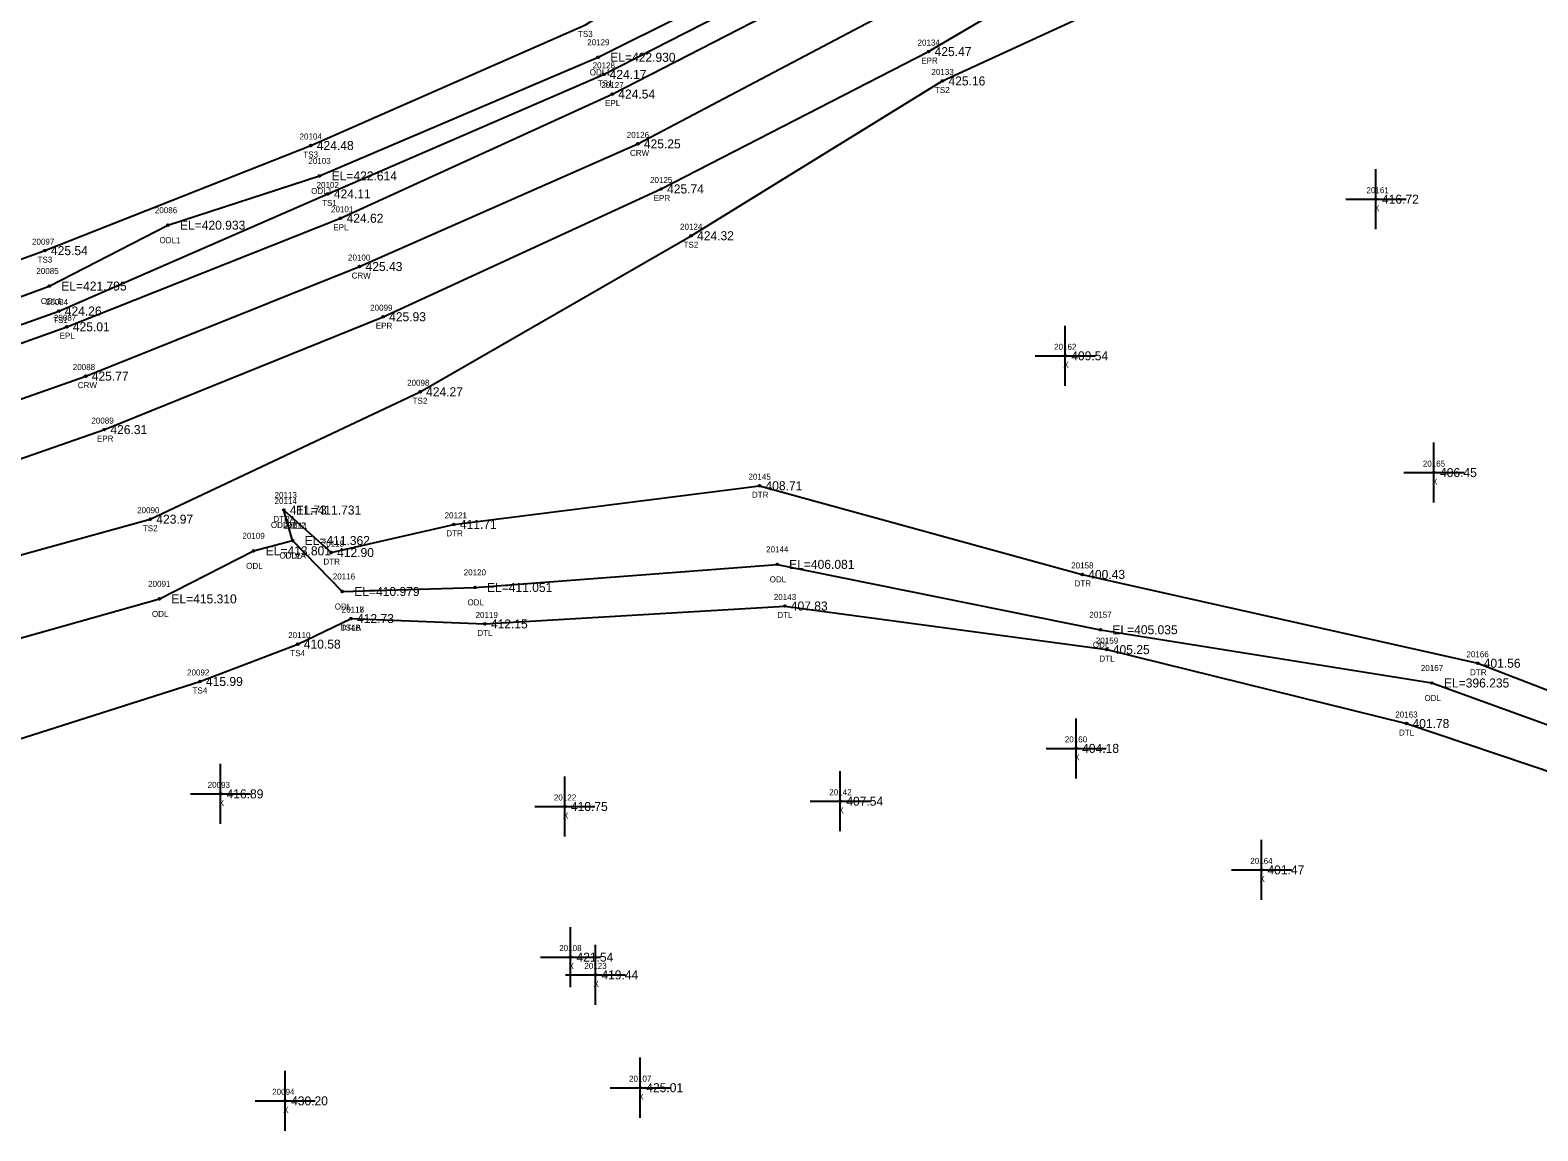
# Model space of a CAD drawing. Extents: x 2116373 to 2118139, y 979529 to 981026.
# Drawn here: x 2116755.3 to 2117006.3, y 979585.4 to 979768.8 of the extents above; entities that cross this region are included whole.
import ezdxf

# ---------------------------------------------------------------- set-up
doc = ezdxf.new("R2010")
doc.units = 0
for name, color, linetype in [('RD_DTM_BkLn1', 7, 'Continuous'), ('RD_DTM_BkLn2', 7, 'Continuous'), ('RD_DTM_BkLn_txCode', 7, 'Continuous'), ('RD_EX_H2O', 7, 'Continuous'), ('RD_EX_H2O_txCode', 7, 'Continuous'), ('RD_EX_Misc', 7, 'Continuous'), ('RD_EX_Misc_txCode', 7, 'Continuous'), ('RD_EX_Road', 7, 'Continuous'), ('RD_EX_Road_txCode', 7, 'Continuous'), ('RD_EX_TX_H2O_ELEV', 7, 'Continuous'), ('RD_EX_TX_Misc_ELEV', 7, 'Continuous'), ('RD_EX_TX_Road_ELEV', 7, 'Continuous'), ('RD_HC_Survey_ELEV', 7, 'Continuous'), ('RD_HC_Survey_txCode', 7, 'Continuous'), ('RD_SMD_Locator', 7, 'Continuous')]:
    doc.layers.add(name, color=color, linetype=linetype)

msp = doc.modelspace()

# ---------------------------------------------------------------- linework, layer by layer
at = {"layer": 'RD_DTM_BkLn1'}
msp.add_lwpolyline([(2116414.21, 979630.19), (2116468.62, 979643.23), (2116521.45, 979653.6), (2116618.87, 979670.38), (2116668.4, 979680.7), (2116717.3, 979694.48), (2116764.56, 979711.13), (2116810.15, 979729.38), (2116856.49, 979749.81), (2116900.74, 979773.15), (2116944.03, 979798.93), (2116982.75, 979824.6), (2117026.56, 979857.02), (2117064.34, 979888.81), (2117101.78, 979922.69), (2117176.3, 979989.4), (2117250.99, 980056.19), (2117326.56, 980126.36)], dxfattribs=at)
at = {"layer": 'RD_DTM_BkLn2'}
for points in [[(2116410.78, 979641.79), (2116465.45, 979654.97), (2116518.83, 979664.89), (2116614.96, 979683.75), (2116663.75, 979692.58), (2116713.02, 979705.22), (2116760.07, 979721.97), (2116804.88, 979741.47), (2116850.79, 979761.38), (2116894.83, 979783.88), (2116937.98, 979807.44), (2116977.39, 979833.6), (2117020.56, 979865.29), (2117056.86, 979896.38), (2117094.29, 979932.2), (2117168.14, 979997.38), (2117238.71, 980069.61), (2117312.33, 980134.21), (2117318.43, 980135.16)], [(2116408.48, 979653.74), (2116461.38, 979665.42), (2116520.7, 979678.48), (2116616.28, 979695.74), (2116661.37, 979703.79), (2116711.18, 979715.21), (2116757.77, 979732.03), (2116802.04, 979749.54), (2116847.76, 979769.63), (2116889.13, 979795.82), (2116931.32, 979820.72), (2116972.01, 979847.71), (2117009.67, 979877.33), (2117051.05, 979910.18), (2117086.71, 979942.74), (2117161.4, 980003.96), (2117222.13, 980080.24), (2117265.44, 980120.03)], [(2116417.57, 979618.2), (2116471.29, 979630.11), (2116523.91, 979640.31), (2116563.87, 979646.21), (2116622.92, 979650.9), (2116673.37, 979660.68), (2116721.38, 979672.44), (2116775.31, 979687.3), (2116820.23, 979708.52), (2116865.35, 979734.51), (2116907.21, 979760.29), (2116934.42, 979772.82), (2116951.5, 979788.78), (2116990.39, 979814.35), (2117033.97, 979847.22), (2117071.26, 979879.46), (2117111.32, 979914.45), (2117184.14, 979980.37), (2117264.18, 980040.84), (2117335.34, 980108.05), (2117336.43, 980115.6)], [(2116420.33, 979611.17), (2116472.25, 979624.85), (2116526.15, 979634.55), (2116564.74, 979640.45), (2116627.58, 979623.31), (2116680.58, 979618.75), (2116744.33, 979647.79), (2116783.58, 979660.27), (2116799.87, 979666.49), (2116808.73, 979670.75)]]:
    msp.add_lwpolyline(points, dxfattribs=at)
at = {"layer": 'RD_EX_H2O'}
msp.add_line((2116799, 979683.75), (2116797.55, 979688.83), dxfattribs=at)
for points in [[(2116411.09, 979644.42), (2116463.93, 979657.73), (2116517.88, 979668.38), (2116615.09, 979686.35), (2116663.35, 979695.16), (2116711.62, 979708.91), (2116758.49, 979726.13), (2116778.25, 979736.27), (2116803.5, 979744.47), (2116849.89, 979764.23), (2116894.14, 979786.32), (2116936.31, 979809.39), (2116976.21, 979834.9), (2117018.41, 979867.86), (2117054.24, 979898.91), (2117093.35, 979934.14), (2117166.11, 979999.69), (2117224.07, 980077.92), (2117265.44, 980120.03)], [(2116797.55, 979688.83), (2116805.41, 979681.75), (2116825.86, 979686.44), (2116876.74, 979692.87), (2116930.48, 979678.1), (2116996.33, 979663.31), (2117099.87, 979623.34), (2117144.47, 979607.97), (2117167, 979599.31)], [(2116419.35, 979615.24), (2116471.51, 979627.15), (2116524.74, 979637.29), (2116564.01, 979643.4), (2116629.25, 979631.55), (2116678.97, 979635.46), (2116738.46, 979663.21), (2116776.82, 979674.03), (2116792.52, 979682.03), (2116799, 979683.75), (2116807.27, 979675.26), (2116829.37, 979675.94), (2116879.68, 979679.78), (2116933.5, 979668.89), (2116988.71, 979660.02), (2117093.78, 979621.95), (2117143.56, 979603.85), (2117167, 979599.31)], [(2116808.73, 979670.75), (2116831.02, 979669.86), (2116880.96, 979672.84), (2116934.58, 979665.58), (2116984.47, 979653.27), (2117095.62, 979615.8), (2117142.6, 979599.29), (2117167, 979599.31)]]:
    msp.add_lwpolyline(points, dxfattribs=at)
at = {"layer": 'RD_EX_Misc'}
for p, q in [((2116979.39, 979735.6), (2116979.39, 979745.6)), ((2116974.39, 979740.6), (2116984.39, 979740.6)), ((2116927.65, 979709.51), (2116927.65, 979719.51)), ((2116922.65, 979714.51), (2116932.65, 979714.51)), ((2116989.05, 979690.06), (2116989.05, 979700.06)), ((2116984.05, 979695.06), (2116994.05, 979695.06)), ((2116929.47, 979644.13), (2116929.47, 979654.13)), ((2116924.47, 979649.13), (2116934.47, 979649.13)), ((2116787.01, 979636.55), (2116787.01, 979646.55)), ((2116844.34, 979634.45), (2116844.34, 979644.45)), ((2116890.2, 979635.33), (2116890.2, 979645.33)), ((2116782.01, 979641.55), (2116792.01, 979641.55)), ((2116839.34, 979639.45), (2116849.34, 979639.45)), ((2116885.2, 979640.33), (2116895.2, 979640.33)), ((2116960.32, 979623.89), (2116960.32, 979633.89)), ((2116955.32, 979628.89), (2116965.32, 979628.89)), ((2116845.27, 979609.36), (2116845.27, 979619.36)), ((2116840.27, 979614.36), (2116850.27, 979614.36)), ((2116849.42, 979606.41), (2116849.42, 979616.41)), ((2116844.42, 979611.41), (2116854.42, 979611.41)), ((2116856.89, 979587.62), (2116856.89, 979597.62)), ((2116797.75, 979585.43), (2116797.75, 979595.43)), ((2116851.89, 979592.62), (2116861.89, 979592.62)), ((2116792.75, 979590.43), (2116802.75, 979590.43))]:
    msp.add_line(p, q, dxfattribs=at)
at = {"layer": 'RD_EX_Road'}
for points in [[(2116412.2, 979638.84), (2116468.17, 979651.36), (2116519.2, 979662.5), (2116617.24, 979678.85), (2116665.51, 979689.1), (2116714.23, 979702.46), (2116761.42, 979719.35), (2116806.99, 979737.42), (2116852.23, 979758.11), (2116896.57, 979780.91), (2116939.1, 979805.52), (2116978.46, 979832.1), (2117021.29, 979863.87), (2117058.15, 979895.61), (2117096.06, 979930.47), (2117170.14, 979995.71), (2117244.91, 980062.82), (2117320.63, 980133.49), (2117326.56, 980126.36)], [(2116416.36, 979621.21), (2116470.51, 979634.11), (2116523.97, 979644.68), (2116620.55, 979661.21), (2116670.7, 979671.96), (2116720.65, 979685.84), (2116767.66, 979702.22), (2116814.07, 979721.02), (2116860.35, 979742.3), (2116904.9, 979765.18), (2116949.06, 979791.19), (2116988.09, 979817.15), (2117031.94, 979849.78), (2117069.79, 979881.53), (2117108.89, 979916.38), (2117182.06, 979982.67), (2117257.56, 980049.29), (2117334.73, 980117.38), (2117326.56, 980126.36)]]:
    msp.add_lwpolyline(points, dxfattribs=at)
at = {"layer": 'RD_SMD_Locator'}
for centre in [(2116904.9, 979765.18), (2116849.89, 979764.23), (2116850.79, 979761.38), (2116907.21, 979760.29), (2116852.23, 979758.11), (2116802.04, 979749.54), (2116856.49, 979749.81), (2116803.5, 979744.47), (2116860.35, 979742.3), (2116804.88, 979741.47), (2116979.39, 979740.6), (2116806.99, 979737.42), (2116778.25, 979736.27), (2116865.35, 979734.51), (2116757.77, 979732.03), (2116810.15, 979729.38), (2116758.49, 979726.13), (2116760.07, 979721.97), (2116814.07, 979721.02), (2116761.42, 979719.35), (2116927.65, 979714.51), (2116764.56, 979711.13), (2116820.23, 979708.52), (2116767.66, 979702.22), (2116989.05, 979695.06), (2116876.74, 979692.87), (2116775.31, 979687.3), (2116797.55, 979688.83), (2116797.55, 979688.83), (2116825.86, 979686.44), (2116792.52, 979682.03), (2116799, 979683.75), (2116799, 979683.75), (2116805.41, 979681.75), (2116879.68, 979679.78), (2116930.48, 979678.1), (2116807.27, 979675.26), (2116829.37, 979675.94), (2116776.82, 979674.03), (2116880.96, 979672.84), (2116808.73, 979670.75), (2116808.73, 979670.75), (2116831.02, 979669.86), (2116933.5, 979668.89), (2116799.87, 979666.49), (2116934.58, 979665.58), (2116996.33, 979663.31), (2116783.58, 979660.27), (2116988.71, 979660.02), (2116984.47, 979653.27), (2116929.47, 979649.13), (2116787.01, 979641.55), (2116844.34, 979639.45), (2116890.2, 979640.33), (2116960.32, 979628.89), (2116845.27, 979614.36), (2116849.42, 979611.41), (2116856.89, 979592.62), (2116797.75, 979590.43)]:
    msp.add_circle(centre, 0.15, dxfattribs=at)

# ---------------------------------------------------------------- texts
at = {"layer": 'RD_DTM_BkLn_txCode'}
for s, p in [('TS3', (2116846.52, 979767.63)), ('20128', (2116848.96, 979762.38)), ('20133', (2116905.37, 979761.29)), ('TS1', (2116849.83, 979759.38)), ('TS2', (2116905.96, 979758.29)), ('20104', (2116800.16, 979750.54)), ('TS3', (2116800.79, 979747.54)), ('20102', (2116803, 979742.47)), ('TS1', (2116803.92, 979739.47)), ('20124', (2116863.51, 979735.51)), ('20097', (2116755.61, 979733.03)), ('TS2', (2116864.1, 979732.51)), ('TS3', (2116756.53, 979730.03)), ('20084', (2116757.91, 979722.97)), ('TS1', (2116759.11, 979719.97)), ('20098', (2116818.07, 979709.52)), ('TS2', (2116818.99, 979706.52)), ('20090', (2116773.12, 979688.3)), ('TS2', (2116774.07, 979685.3)), ('20117', (2116807.18, 979671.75)), ('TS4B', (2116807.01, 979668.75)), ('20110', (2116798.27, 979667.49)), ('TS4', (2116798.62, 979664.49)), ('20092', (2116781.43, 979661.27)), ('TS4', (2116782.34, 979658.27))]:
    msp.add_text(s, height=1, dxfattribs=at).set_placement(p)
at = {"layer": 'RD_EX_H2O_txCode'}
for s, p in [('20129', (2116848.05, 979766.23)), ('ODL1', (2116848.48, 979761.23)), ('20103', (2116801.63, 979746.47)), ('ODL1', (2116802.09, 979741.47)), ('20086', (2116776.07, 979738.27)), ('ODL1', (2116776.84, 979733.27)), ('20085', (2116756.33, 979728.13)), ('ODL1', (2116757.08, 979723.13)), ('20145', (2116874.91, 979693.87)), ('20113', (2116796, 979690.83)), ('20114', (2116796, 979689.83)), ('DTR', (2116875.48, 979690.87)), ('DTRA', (2116795.8, 979686.83)), ('20121', (2116824.31, 979687.44)), ('20109', (2116790.65, 979684.03)), ('ODL2B', (2116795.39, 979685.83)), ('20112', (2116797.45, 979685.75)), ('20111', (2116797.74, 979685.75)), ('DTR', (2116824.6, 979684.44)), ('20115', (2116803.86, 979682.75)), ('20144', (2116877.85, 979681.78)), ('ODL', (2116791.28, 979679.03)), ('ODL2A', (2116796.82, 979680.75)), ('ODL', (2116797.76, 979680.75)), ('DTR', (2116804.14, 979679.75)), ('20158', (2116928.64, 979679.1)), ('20091', (2116774.95, 979676.03)), ('20116', (2116805.69, 979677.26)), ('20120', (2116827.49, 979677.94)), ('ODL', (2116878.44, 979676.78)), ('DTR', (2116929.21, 979676.1)), ('20143', (2116879.13, 979673.84)), ('ODL', (2116775.58, 979671.03)), ('ODL', (2116806.02, 979672.26)), ('20118', (2116807.18, 979671.75)), ('ODL', (2116828.12, 979672.94)), ('20119', (2116829.47, 979670.86)), ('20157', (2116931.66, 979670.89)), ('DTLA', (2116807, 979668.75)), ('DTL', (2116879.72, 979670.84)), ('DTL', (2116829.77, 979667.86)), ('ODL', (2116932.25, 979665.89)), ('20159', (2116932.75, 979666.58)), ('DTL', (2116933.34, 979663.58)), ('20166', (2116994.45, 979664.31)), ('20167', (2116986.86, 979662.02)), ('DTR', (2116995.06, 979661.31)), ('ODL', (2116987.47, 979657.02)), ('20163', (2116982.61, 979654.27)), ('DTL', (2116983.22, 979651.27))]:
    msp.add_text(s, height=1, dxfattribs=at).set_placement(p)
at = {"layer": 'RD_EX_Misc_txCode'}
for s, p in [('20161', (2116977.81, 979741.6)), ('X', (2116979.07, 979738.6)), ('20162', (2116925.79, 979715.51)), ('X', (2116927.34, 979712.51)), ('20165', (2116987.19, 979696.06)), ('X', (2116988.74, 979693.06)), ('20160', (2116927.58, 979650.13)), ('X', (2116929.16, 979647.13)), ('20093', (2116784.86, 979642.55)), ('20142', (2116888.36, 979641.33)), ('X', (2116786.7, 979639.55)), ('20122', (2116842.51, 979640.45)), ('X', (2116889.88, 979638.33)), ('X', (2116844.03, 979637.45)), ('20164', (2116958.46, 979629.89)), ('X', (2116960, 979626.89)), ('20108', (2116843.4, 979615.36)), ('X', (2116844.95, 979612.36)), ('20123', (2116847.58, 979612.41)), ('X', (2116849.1, 979609.41)), ('20107', (2116855.02, 979593.62)), ('20094', (2116795.6, 979591.43)), ('X', (2116856.58, 979590.62)), ('X', (2116797.44, 979588.43))]:
    msp.add_text(s, height=1, dxfattribs=at).set_placement(p)
at = {"layer": 'RD_EX_Road_txCode'}
for s, p in [('20134', (2116903.06, 979766.18)), ('EPR', (2116903.67, 979763.18)), ('20127', (2116850.4, 979759.11)), ('EPL', (2116851.03, 979756.11)), ('20125', (2116858.51, 979743.3)), ('EPR', (2116859.12, 979740.3)), ('20101', (2116805.4, 979738.42)), ('EPL', (2116805.78, 979735.42)), ('20099', (2116811.92, 979722.02)), ('20087', (2116759.26, 979720.35)), ('EPR', (2116812.85, 979719.02)), ('EPL', (2116760.21, 979717.35)), ('20089', (2116765.5, 979703.22)), ('EPR', (2116766.43, 979700.22))]:
    msp.add_text(s, height=1, dxfattribs=at).set_placement(p)
at = {"layer": 'RD_EX_TX_H2O_ELEV'}
for s, p in [('EL=422.930', (2116851.89, 979763.48)), ('EL=422.614', (2116805.5, 979743.72)), ('EL=420.933', (2116780.25, 979735.52)), ('EL=421.795', (2116760.49, 979725.38)), ('408.71', (2116877.74, 979692.12)), ('411.73', (2116798.55, 979688.08)), ('EL=411.731', (2116799.55, 979688.08)), ('411.71', (2116826.86, 979685.69)), ('EL=411.362', (2116801, 979683)), ('EL=411.362', (2116801, 979683)), ('EL=413.801', (2116794.52, 979681.28)), ('412.90', (2116806.41, 979681)), ('EL=406.081', (2116881.68, 979679.03)), ('400.43', (2116931.48, 979677.35)), ('EL=415.310', (2116778.82, 979673.28)), ('EL=410.979', (2116809.27, 979674.51)), ('EL=411.051', (2116831.37, 979675.19)), ('407.83', (2116881.96, 979672.09)), ('412.73', (2116809.73, 979670)), ('412.15', (2116832.02, 979669.11)), ('EL=405.035', (2116935.5, 979668.14)), ('405.25', (2116935.58, 979664.83)), ('401.56', (2116997.33, 979662.56)), ('EL=396.235', (2116990.71, 979659.27)), ('401.78', (2116985.47, 979652.52))]:
    msp.add_text(s, height=1.5, dxfattribs=at).set_placement(p)
at = {"layer": 'RD_EX_TX_Misc_ELEV'}
for s, p in [('424.17', (2116851.79, 979760.63)), ('425.16', (2116908.21, 979759.54)), ('424.48', (2116803.04, 979748.79)), ('424.11', (2116805.88, 979740.72)), ('416.72', (2116980.39, 979739.85)), ('424.32', (2116866.35, 979733.76)), ('425.54', (2116758.77, 979731.28)), ('424.26', (2116761.07, 979721.22)), ('409.54', (2116928.65, 979713.76)), ('424.27', (2116821.23, 979707.77)), ('406.45', (2116990.05, 979694.31)), ('423.97', (2116776.31, 979686.55)), ('412.73', (2116809.73, 979670)), ('410.58', (2116800.87, 979665.74)), ('415.99', (2116784.58, 979659.52)), ('404.18', (2116930.47, 979648.38)), ('416.89', (2116788.01, 979640.8)), ('410.75', (2116845.34, 979638.7)), ('407.54', (2116891.2, 979639.58)), ('401.47', (2116961.32, 979628.14)), ('421.54', (2116846.27, 979613.61)), ('419.44', (2116850.42, 979610.66)), ('425.01', (2116857.89, 979591.87)), ('430.20', (2116798.75, 979589.68))]:
    msp.add_text(s, height=1.5, dxfattribs=at).set_placement(p)
at = {"layer": 'RD_EX_TX_Road_ELEV'}
for s, p in [('425.47', (2116905.9, 979764.43)), ('424.54', (2116853.23, 979757.36)), ('425.74', (2116861.35, 979741.55)), ('424.62', (2116807.99, 979736.67)), ('425.01', (2116762.42, 979718.6)), ('425.93', (2116815.07, 979720.27)), ('426.31', (2116768.66, 979701.47))]:
    msp.add_text(s, height=1.5, dxfattribs=at).set_placement(p)
at = {"layer": 'RD_HC_Survey_ELEV'}
for s, p in [('425.25', (2116857.49, 979749.06)), ('425.43', (2116811.15, 979728.63)), ('425.77', (2116765.56, 979710.38))]:
    msp.add_text(s, height=1.5, dxfattribs=at).set_placement(p)
at = {"layer": 'RD_HC_Survey_txCode'}
for s, p in [('20126', (2116854.64, 979750.81)), ('CRW', (2116855.18, 979747.81)), ('20100', (2116808.23, 979730.38)), ('CRW', (2116808.83, 979727.38)), ('20088', (2116762.4, 979712.13)), ('CRW', (2116763.24, 979709.13))]:
    msp.add_text(s, height=1, dxfattribs=at).set_placement(p)

doc.saveas('drawing.dxf')
